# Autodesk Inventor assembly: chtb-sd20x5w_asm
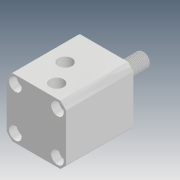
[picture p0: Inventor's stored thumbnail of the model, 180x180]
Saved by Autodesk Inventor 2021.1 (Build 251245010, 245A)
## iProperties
Company: Microsoft
Created: 2018-05
Part Number: chtb-sd20x5w_asm
Description: STEP AP214
Document SubType Name: Assembly
Designer: user
Title: chtb-sd20x5w_asm.STEP
Author: Windows
Revision Number: ÈÎºÎ
Sending System: SolidWorks 2015
Preprocessor: SwSTEP 2.0
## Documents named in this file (4)
- D:\Vault_2016\Projekty\Clamptek\Hydraulic\CHTB\CHTB-20\Inventor\CHTB-SD20x5W\chtb-sd20x5w_asm.iam
- D:\Vault_2016\Projekty\Clamptek\Hydraulic\CHTB\CHTB-20\Inventor\CHTB-SD20x5W\CHTB-SD20X5NBT.ipt
- D:\Vault_2016\Projekty\Clamptek\Hydraulic\CHTB\CHTB-20\Inventor\CHTB-SD20x5W\CHTB-SD20X5WHSG.ipt
- D:\Vault_2016\Projekty\Clamptek\Hydraulic\CHTB\CHTB-20\Inventor\CHTB-SD20x5W\QG.ipt
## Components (3 placed, 3 different names)
1. CHTB-SD20X5NBT_1
2. CHTB-SD20X5WHSG_2
3. QG_3
